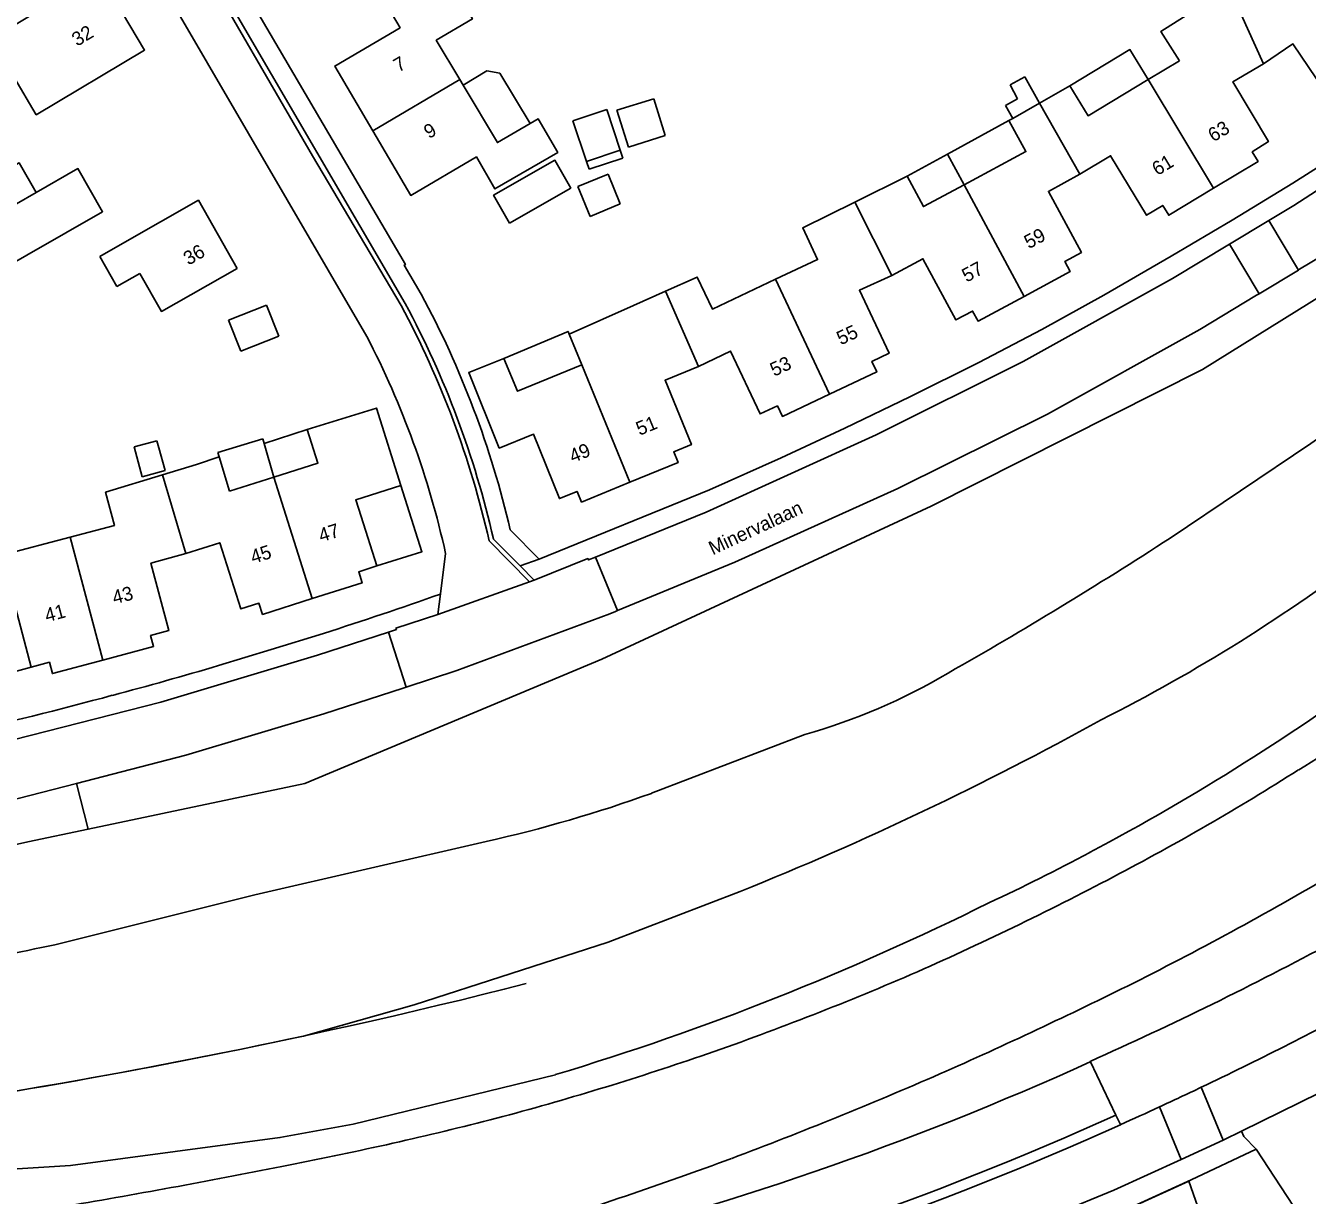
# Model space of a CAD drawing. Extents: x 194485 to 197793, y 468269 to 470822.
# Drawn here: x 195647.3 to 195758.3, y 469332.6 to 469433.9 of the extents above; entities that cross this region are included whole.
import ezdxf

# ---------------------------------------------------------------- set-up
doc = ezdxf.new("R2010")
doc.units = 0
for name, color, linetype in [('BGT grensvlak begroeid terreindeel', 7, 'Continuous'), ('BGT grensvlak gebouwinstallatie plus 1', 7, 'Continuous'), ('BGT grensvlak overig bouwwerk uitbreiding populatie', 7, 'Continuous'), ('BGT grensvlak pand op maaiveld', 7, 'Continuous'), ('BGT grensvlak pand op maaiveld LR', 7, 'Continuous'), ('BGT grensvlak vegetatieobject', 7, 'Continuous'), ('BGT grensvlak waterdeel', 7, 'Continuous'), ('BGT grensvlak wegdeel', 7, 'Continuous'), ('BGT lijnelement scheiding walbescherming', 7, 'Continuous'), ('BGT tekst huisnummerreeks', 7, 'Continuous'), ('BGT tekst openbare ruimte label weg', 7, 'Continuous'), ('GEM grensvlak WOZ_BRK percelen', 7, 'Continuous')]:
    doc.layers.add(name, color=color, linetype=linetype)

msp = doc.modelspace()

# ---------------------------------------------------------------- linework, layer by layer
at = {"layer": 'BGT grensvlak begroeid terreindeel'}
for p, q in [((195771.89, 469418.23), (195749.21, 469404.12)), ((195749.21, 469404.12), (195725.71, 469392.27)), ((195725.71, 469392.27), (195697.19, 469379.04)), ((195697.19, 469379.04), (195671.48, 469368.26)), ((195651.71, 469368.28), (195652.7, 469364.31)), ((195652.7, 469364.31), (195671.48, 469368.26))]:
    msp.add_line(p, q, dxfattribs=at)
msp.add_lwpolyline([(195626.43, 469358.76), (195629.8, 469359.24), (195647.49, 469363.23), (195652.7, 469364.31)], dxfattribs=at)
at = {"layer": 'BGT grensvlak gebouwinstallatie plus 1'}
for p, q in [((195685.18, 469428.74), (195687.24, 469429.98)), ((195687.24, 469429.98), (195688.35, 469429.79)), ((195688.35, 469429.79), (195690.99, 469425.43)), ((195727.14, 469422.77), (195732.46, 469425.68)), ((195699.01, 469422.42), (195696.1, 469421.45)), ((195698.78, 469423.1), (195699.01, 469422.42)), ((195723.64, 469420.86), (195727.14, 469422.77)), ((195728.57, 469420.12), (195727.14, 469422.77)), ((195696.1, 469421.45), (195695.87, 469422.13)), ((195667.95, 469397.71), (195671.68, 469398.91)), ((195656.7, 469397.41), (195658.67, 469397.95)), ((195658.67, 469397.95), (195658.83, 469397.34)), ((195663.95, 469396.92), (195667.84, 469398.11)), ((195667.84, 469398.11), (195667.95, 469397.71)), ((195657.4, 469394.83), (195656.7, 469397.41)), ((195658.83, 469397.34), (195659.37, 469395.36)), ((195664.06, 469396.54), (195663.95, 469396.92)), ((195667.95, 469397.71), (195668.8, 469394.79)), ((195659.37, 469395.36), (195657.4, 469394.83)), ((195647.78, 469378.34), (195644.71, 469377.51))]:
    msp.add_line(p, q, dxfattribs=at)
for points in [[(195737.73, 469428.69), (195742.94, 469431.82), (195744.51, 469429.22)], [(195648.2, 469419.44), (195646.73, 469422.02), (195640.6, 469418.52), (195642.07, 469415.94)], [(195694.37, 469407.17), (195694.27, 469407.41), (195688.71, 469405.07)], [(195677.72, 469387.11), (195681.61, 469388.33), (195679.8, 469394.08)]]:
    msp.add_lwpolyline(points, dxfattribs=at)
at = {"layer": 'BGT grensvlak overig bouwwerk uitbreiding populatie'}
for p, q in [((195732.56, 469428.76), (195733.83, 469429.46)), ((195733.83, 469429.46), (195735.1, 469427.18)), ((195733.21, 469427.55), (195732.56, 469428.76)), ((195694.7, 469425.66), (195697.62, 469426.62)), ((195697.62, 469426.62), (195698.78, 469423.1)), ((195698.5, 469426.57), (195701.7, 469427.56)), ((195701.7, 469427.56), (195702.69, 469424.38)), ((195732.16, 469426.99), (195733.21, 469427.55)), ((195732.79, 469425.86), (195732.16, 469426.99)), ((195695.87, 469422.13), (195694.7, 469425.66)), ((195699.5, 469423.38), (195698.5, 469426.57)), ((195702.69, 469424.38), (195699.5, 469423.38)), ((195695.87, 469422.13), (195698.78, 469423.1)), ((195695.12, 469419.95), (195697.74, 469421.02)), ((195697.74, 469421.02), (195698.79, 469418.45)), ((195696.18, 469417.37), (195695.12, 469419.95)), ((195698.79, 469418.45), (195696.18, 469417.37)), ((195664.86, 469408.39), (195668.15, 469409.7)), ((195668.15, 469409.7), (195669.22, 469406.99)), ((195665.93, 469405.69), (195664.86, 469408.39)), ((195669.22, 469406.99), (195665.93, 469405.69))]:
    msp.add_line(p, q, dxfattribs=at)
at = {"layer": 'BGT grensvlak pand op maaiveld'}
for p, q in [((195747.22, 469430.85), (195744.51, 469429.22)), ((195684.89, 469429.22), (195685.18, 469428.74)), ((195737.73, 469428.69), (195735.1, 469427.18)), ((195735.1, 469427.18), (195732.79, 469425.86)), ((195732.79, 469425.86), (195732.46, 469425.68)), ((195719.12, 469418.61), (195723.64, 469420.86)), ((195648.2, 469419.44), (195642.07, 469415.94)), ((195653.72, 469413.9), (195655.69, 469415.03)), ((195655.2, 469411.3), (195653.72, 469413.9)), ((195657.18, 469412.43), (195655.2, 469411.3)), ((195702.7, 469410.89), (195699.93, 469409.65)), ((195699.93, 469409.65), (195694.37, 469407.17)), ((195694.37, 469407.17), (195695.46, 469404.52)), ((195659.15, 469395), (195662.09, 469395.9)), ((195662.09, 469395.9), (195664.06, 469396.54)), ((195664.06, 469396.54), (195664.95, 469393.58)), ((195664.95, 469393.58), (195668.8, 469394.79))]:
    msp.add_line(p, q, dxfattribs=at)
for points in [[(195684.89, 469429.22), (195682.85, 469432.63), (195685.99, 469434.47), (195683.06, 469439.38), (195678.11, 469436.48), (195679.73, 469433.71), (195674.07, 469430.39), (195677.36, 469424.79)], [(195644.32, 469432.76), (195648.22, 469426.18), (195657.6, 469431.78), (195653.69, 469438.36), (195644.32, 469432.76)], [(195748.12, 469434.96), (195745.62, 469433.39), (195747.22, 469430.85)], [(195766.1, 469429.94), (195762.35, 469427.41), (195761.78, 469428.24), (195760.42, 469427.32), (195757.05, 469432.31), (195754.51, 469430.59)], [(195750.17, 469419.81), (195754.04, 469422.14), (195753.53, 469422.96), (195754.93, 469423.85), (195751.85, 469429.04), (195754.51, 469430.59)], [(195744.51, 469429.22), (195739.31, 469426.09), (195737.73, 469428.69)], [(195685.18, 469428.74), (195688.16, 469423.77), (195690.99, 469425.43)], [(195690.99, 469425.43), (195691.67, 469425.83), (195693.38, 469422.92), (195687.94, 469419.76), (195686.33, 469422.53), (195680.65, 469419.19), (195677.36, 469424.79)], [(195732.46, 469425.68), (195733.92, 469422.99), (195728.57, 469420.12)], [(195689.19, 469416.79), (195694.51, 469419.83), (195693.14, 469422.23), (195687.82, 469419.2), (195689.19, 469416.79)], [(195750.17, 469419.81), (195746.29, 469417.48), (195745.77, 469418.32), (195744.37, 469417.48), (195741.26, 469422.62), (195738.6, 469421.03)], [(195642.07, 469415.94), (195644.2, 469412.2), (195653.96, 469417.77), (195651.83, 469421.51), (195648.2, 469419.44)], [(195723.64, 469420.86), (195725.05, 469418.22), (195728.57, 469420.12)], [(195733.77, 469410.45), (195737.75, 469412.59), (195737.29, 469413.46), (195738.73, 469414.25), (195735.87, 469419.53), (195738.6, 469421.03)], [(195665.62, 469412.87), (195662.26, 469418.77), (195655.69, 469415.03)], [(195719.12, 469418.61), (195714.6, 469416.37), (195715.88, 469413.64), (195712.24, 469411.93)], [(195733.77, 469410.45), (195729.79, 469408.31), (195729.31, 469409.18), (195727.86, 469408.41), (195725.01, 469413.71), (195722.3, 469412.25)], [(195657.18, 469412.43), (195659.06, 469409.14), (195665.62, 469412.87)], [(195716.92, 469401.99), (195721.01, 469403.91), (195720.59, 469404.82), (195722.08, 469405.52), (195719.5, 469410.98), (195722.3, 469412.25)], [(195712.24, 469411.93), (195706.78, 469409.35), (195705.46, 469412.12), (195702.7, 469410.89)], [(195716.92, 469401.99), (195712.83, 469400.06), (195712.4, 469400.96), (195710.91, 469400.27), (195708.35, 469405.71), (195705.56, 469404.37)], [(195699.62, 469394.35), (195695.44, 469392.64), (195695.05, 469393.56), (195693.53, 469392.94), (195691.27, 469398.52), (195688.31, 469397.31), (195685.67, 469403.85), (195688.71, 469405.07)], [(195688.71, 469405.07), (195689.9, 469402.24), (195695.46, 469404.52)], [(195699.62, 469394.35), (195703.8, 469396.06), (195703.43, 469396.98), (195704.95, 469397.62), (195702.68, 469403.19), (195705.56, 469404.37)], [(195679.8, 469394.08), (195677.68, 469400.78), (195671.68, 469398.91)], [(195671.68, 469398.91), (195672.61, 469396), (195668.8, 469394.79)], [(195659.15, 469395), (195654.22, 469393.49), (195654.98, 469390.6), (195651.16, 469389.59)], [(195677.72, 469387.11), (195676.36, 469391.38), (195675.88, 469392.84), (195679.8, 469394.08)], [(195651.16, 469389.59), (195645.23, 469388.03), (195644.47, 469390.96)], [(195672.12, 469384.28), (195667.81, 469382.91), (195667.5, 469383.87), (195665.93, 469383.38), (195664.11, 469389.11), (195661.16, 469388.18)], [(195661.16, 469388.18), (195658.15, 469387.34), (195659.7, 469381.51), (195658.11, 469381.08), (195658.37, 469380.12), (195653.99, 469378.96)], [(195672.12, 469384.28), (195676.43, 469385.64), (195676.15, 469386.61), (195677.72, 469387.11)], [(195647.78, 469378.34), (195646.24, 469384.16), (195643.24, 469383.39)], [(195653.99, 469378.96), (195649.62, 469377.79), (195649.36, 469378.77), (195647.78, 469378.34)]]:
    msp.add_lwpolyline(points, dxfattribs=at)
at = {"layer": 'BGT grensvlak pand op maaiveld LR'}
for p, q in [((195754.51, 469430.59), (195751.54, 469437.11)), ((195684.89, 469429.22), (195677.36, 469424.79)), ((195744.51, 469429.22), (195750.17, 469419.81)), ((195738.6, 469421.03), (195735.1, 469427.18)), ((195728.57, 469420.12), (195733.77, 469410.45)), ((195722.3, 469412.25), (195719.12, 469418.61)), ((195712.24, 469411.93), (195716.92, 469401.99)), ((195705.56, 469404.37), (195702.7, 469410.89)), ((195695.46, 469404.52), (195699.62, 469394.35)), ((195661.16, 469388.18), (195659.15, 469395)), ((195668.8, 469394.79), (195672.12, 469384.28)), ((195651.16, 469389.59), (195653.99, 469378.96))]:
    msp.add_line(p, q, dxfattribs=at)
at = {"layer": 'BGT grensvlak vegetatieobject'}
msp.add_line((195739.49, 469344.2), (195739.51, 469344.16), dxfattribs=at)
msp.add_lwpolyline([(195629.9, 469333.85), (195651.17, 469335.18), (195669.32, 469337.6), (195675.67, 469338.78), (195693.18, 469343.05)], dxfattribs=at)
for centre, radius, start, end in [((195644.55, 469541.54), 202.82, 297.8972, 306.6437), ((195644.48, 469541.65), 202.96, 295.1463, 297.8997), ((195624.16, 469572), 239.12, 286.7773, 296.4634), ((195606.88, 469640.95), 325.03, 294.0792, 298.2028)]:
    msp.add_arc(centre, radius, start, end, dxfattribs=at)
at = {"layer": 'BGT grensvlak waterdeel'}
msp.add_line((195701.49, 469367.42), (195714.79, 469372.52), dxfattribs=at)
for points in [[(195746.42, 469389.51), (195758.61, 469397.72), (195771.32, 469406.63)], [(195649.83, 469354.3), (195667.14, 469358.62), (195687.18, 469363.25)], [(195709.18, 469358.92), (195697.74, 469354.54), (195680.94, 469349.09), (195671.36, 469346.4)]]:
    msp.add_lwpolyline(points, dxfattribs=at)
for centre, radius, start, end in [((195525.96, 469730.75), 406.26, 299.6928, 302.864), ((195674.46, 469505.11), 146.97, 296.6736, 307.4694), ((195700.76, 469422.38), 51.8, 285.7121, 300.6885), ((195604.72, 469618.96), 280.24, 291.8842, 298.9657), ((195661.2, 469479.16), 118.79, 282.6319, 289.8279), ((195614.7, 469517.51), 166.94, 275.5449, 282.1494), ((195557.61, 469873.73), 539.46, 277.6234, 282.1728)]:
    msp.add_arc(centre, radius, start, end, dxfattribs=at)
at = {"layer": 'BGT grensvlak wegdeel'}
for p, q in [((195651.27, 469459.36), (195680.17, 469409.84)), ((195676.84, 469406.98), (195648.06, 469456.35)), ((195751.55, 469414.96), (195754.95, 469417.01)), ((195754.95, 469417.01), (195755.26, 469417.19)), ((195757.52, 469412.73), (195754.95, 469417.01)), ((195754.12, 469410.68), (195751.55, 469414.96)), ((195757.52, 469412.73), (195754.12, 469410.68)), ((195757.61, 469412.79), (195757.52, 469412.73)), ((195754.12, 469410.68), (195753.9, 469410.55)), ((195691.78, 469387.69), (195689.26, 469390.23)), ((195687.44, 469389.28), (195690.93, 469385.73)), ((195687.8, 469389.46), (195690.13, 469387.11)), ((195683.22, 469384.68), (195683.67, 469388.18)), ((195698.55, 469383.24), (195696.64, 469387.87)), ((195690.13, 469387.11), (195691.78, 469387.69)), ((195690.13, 469387.11), (195691.34, 469385.88)), ((195682.99, 469382.91), (195690.93, 469385.73)), ((195690.93, 469385.73), (195691.34, 469385.88)), ((195682.99, 469382.91), (195683.22, 469384.68)), ((195698.55, 469383.24), (195698.37, 469383.16)), ((195680.25, 469376.62), (195678.71, 469381.37)), ((195680.25, 469376.62), (195679.98, 469376.53)), ((195741.71, 469339.55), (195739.51, 469344.16)), ((195749.11, 469341.96), (195751.02, 469337.39)), ((195752.59, 469338.16), (195759.35, 469341.47)), ((195747.38, 469335.72), (195745.49, 469340.26)), ((195742.11, 469338.73), (195741.71, 469339.55)), ((195747.38, 469335.72), (195751.02, 469337.39)), ((195753.87, 469336.59), (195760.99, 469325.74))]:
    msp.add_line(p, q, dxfattribs=at)
for points in [[(195648.31, 469463.39), (195661.65, 469440.73), (195672.14, 469422.63), (195679.82, 469409.65)], [(195681.56, 469410.64), (195680.09, 469413.16), (195680.18, 469413.2), (195652.65, 469460.18)], [(195691.78, 469387.69), (195706.53, 469393.71), (195712.72, 469396.47), (195718.24, 469399.03), (195723.88, 469401.74), (195729.84, 469404.73), (195735.29, 469407.57), (195740.68, 469410.56), (195746.5, 469413.93), (195751.8, 469417.05), (195757.04, 469420.26), (195762.74, 469423.85), (195767.87, 469427.26), (195772.95, 469430.76), (195778.38, 469434.67), (195783.37, 469438.36), (195788.25, 469442.06), (195794.43, 469446.9)], [(195755.26, 469417.19), (195757.14, 469418.33), (195768.98, 469426), (195780.09, 469433.85), (195792.6, 469443.28), (195794.92, 469445.13), (195796.98, 469447.08)], [(195771.71, 469421.85), (195759.62, 469414), (195757.61, 469412.79)], [(195696.64, 469387.87), (195706.22, 469391.77), (195720.95, 469398.46), (195733.68, 469404.81), (195746.62, 469411.99), (195751.55, 469414.96)], [(195753.9, 469410.55), (195748.98, 469407.59), (195735.79, 469400.25), (195722.83, 469393.82), (195708.72, 469387.43), (195698.55, 469383.24)], [(195691.34, 469385.88), (195695.99, 469387.75), (195696.04, 469387.63), (195696.64, 469387.87)], [(195682.99, 469382.91), (195679.37, 469381.72), (195679.4, 469381.59), (195678.71, 469381.37)], [(195698.37, 469383.16), (195697.89, 469382.97), (195684.64, 469378.05), (195680.25, 469376.62)], [(195678.71, 469381.37), (195672.58, 469379.37), (195658.99, 469375.31), (195644.84, 469371.7), (195631.45, 469368.79), (195622.36, 469367.14)], [(195673.09, 469381.27), (195668.55, 469379.87), (195664.01, 469378.48)], [(195679.98, 469376.53), (195673.11, 469374.3), (195661.16, 469370.72), (195651.71, 469368.28)], [(195651.71, 469368.28), (195646.64, 469366.97), (195632.48, 469363.86), (195626.9, 469362.86)], [(195751.02, 469337.39), (195751.07, 469337.41), (195752.59, 469338.16)], [(195753.87, 469336.59), (195752.81, 469337.71), (195752.59, 469338.16)], [(195705.11, 469317.85), (195711.09, 469319.54), (195716.2, 469321.18), (195721.64, 469323.06), (195726.92, 469324.98), (195732.23, 469327.01), (195737.5, 469329.18), (195742.86, 469331.49), (195748.25, 469333.94), (195753.87, 469336.59)], [(195705.49, 469320.04), (195713.1, 469322.22), (195727.24, 469327.17), (195741.55, 469333.05), (195747.38, 469335.72)]]:
    msp.add_lwpolyline(points, dxfattribs=at)
for centre, radius, start, end in [((195610.11, 469372), 81.22, 12.9707, 28.4016), ((195609.06, 469371.58), 80.35, 12.7248, 28.2868), ((195609.04, 469371.57), 80.77, 12.7972, 28.2853), ((195608.87, 469371.66), 76.6, 12.4558, 27.4629), ((195577.82, 469681.24), 314.74, 287.6196, 289.5656), ((195647.71, 469546.97), 208.76, 301.7454, 307.3719), ((195574.76, 469679.05), 313.54, 284.7923, 286.5384), ((195568.52, 469693.45), 329.06, 280.2302, 285.2011), ((195636.99, 469559.78), 225.3, 297.6435, 302.3495), ((195609.5, 469611.3), 283.7, 293.7956, 297.7335), ((195614.81, 469607.16), 286.56, 296.6258, 300.7141), ((195615.81, 469603.37), 273.91, 289.1763, 293.2568), ((195549.31, 469741.93), 436.4, 293.953, 296.384), ((195606.31, 469642.05), 332.33, 295.4488, 298.2148), ((195621.29, 469590.84), 260.27, 284.8681, 288.9426), ((195628.96, 469587.01), 266.82, 283.4409, 294.475), ((195577.55, 469684.4), 372.36, 290.5803, 293.5757), ((195367.12, 470152.96), 896.46, 294.96502, 295.22092), ((195611.22, 469631.39), 320.6, 294.0942, 294.758), ((195606.22, 469660.55), 331.54, 281.1023, 284.2939), ((195626.71, 469593.4), 278.68, 283.5994, 294.3718), ((195625.65, 469596.54), 282.9, 283.6612, 294.3096), ((195573.57, 469702.32), 390.55, 287.3426, 290.2022), ((195544.07, 469963.56), 640.84, 279.5957, 281.33888)]:
    msp.add_arc(centre, radius, start, end, dxfattribs=at)
at = {"layer": 'BGT lijnelement scheiding walbescherming'}
msp.add_arc((195557.58, 469873.89), 539.62, 277.6238, 284.2765, dxfattribs=at)
at = {"layer": 'GEM grensvlak WOZ_BRK percelen'}
msp.add_lwpolyline([(195751.75, 469306.03), (195757.14, 469307.92), (195748.04, 469333.84), (195742.83, 469331.47)], dxfattribs=at)

# ---------------------------------------------------------------- texts
at = {"layer": 'BGT tekst huisnummerreeks'}
for s, rotation, p in [('32', 30.7, (195651.75, 469432.06)), ('7', 30.5, (195679.6, 469429.82)), ('63', 31, (195750.16, 469423.78)), ('9', 30.5, (195682.23, 469424.06)), ('61', 31, (195745.31, 469420.86)), ('59', 28.3, (195734.18, 469414.53)), ('36', 30, (195661.4, 469413.1)), ('57', 28.3, (195728.79, 469411.63)), ('55', 25.2, (195717.89, 469406.2)), ('53', 25.2, (195712.12, 469403.48)), ('51', 22.3, (195700.46, 469398.37)), ('49', 22.3, (195694.68, 469396)), ('47', 17.6, (195672.89, 469389.14)), ('45', 17.6, (195666.99, 469387.28)), ('43', 14.9, (195654.98, 469383.77)), ('41', 14.9, (195649.13, 469382.22))]:
    msp.add_text(s, height=1.2, rotation=rotation, dxfattribs=at).set_placement(p)
at = {"layer": 'BGT tekst openbare ruimte label weg'}
msp.add_text('Minervalaan', height=1.2, rotation=25, dxfattribs=at).set_placement((195706.8, 469388.02))

doc.saveas('drawing.dxf')
